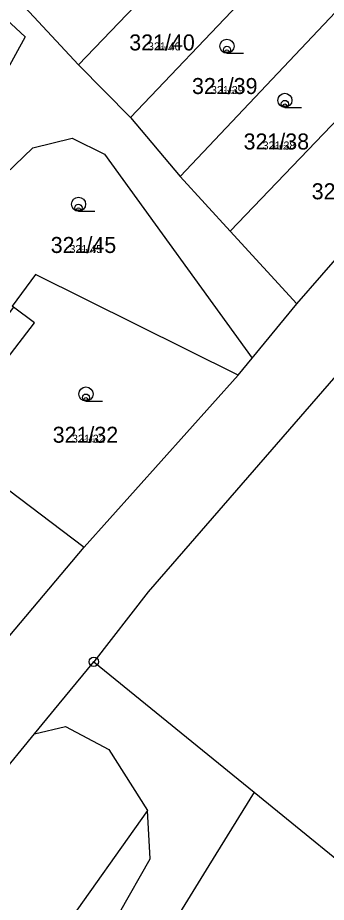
# Model space of a CAD drawing. Extents: x -744652 to -739090, y -980828 to -975855.
# Drawn here: x -742287.7 to -742254.9, y -979035.7 to -978941.8 of the extents above; entities that cross this region are included whole.
import ezdxf

# ---------------------------------------------------------------- set-up
doc = ezdxf.new("R2010")
doc.units = 0
for name, color, linetype in [('KAT_02_hranice parcel', 7, 'Continuous'), ('KAT_03_1000_čísla parcelní', 7, 'Continuous'), ('KAT_03_100_čísla parcelní', 7, 'Continuous'), ('KAT_03_250_čísla parcelní', 7, 'Continuous'), ('KAT_03_500_čísla parcelní', 7, 'Continuous'), ('KAT_05_1000_značky kultur', 7, 'Continuous'), ('KAT_05_100_značky kultur', 7, 'Continuous'), ('KAT_05_250_značky kultur', 7, 'Continuous'), ('KAT_05_500_značky kultur', 7, 'Continuous'), ('KAT_11_značky bodu BP', 7, 'Continuous'), ('KAT_14_plocha_budovy', 7, 'Continuous')]:
    doc.layers.add(name, color=color, linetype=linetype)

msp = doc.modelspace()

# ---------------------------------------------------------------- linework, layer by layer
at = {"layer": 'KAT_02_hranice parcel'}
for p, q in [((-742263.37, -978928.16), (-742281.23, -978946.79)), ((-742213.59, -978933.42), (-742273.84, -979002.73)), ((-742261.82, -978937.76), (-742275.69, -978952.38)), ((-742251.42, -978938.5), (-742270.43, -978958.65)), ((-742286.94, -978940.67), (-742281.23, -978946.79)), ((-742281.23, -978946.79), (-742275.69, -978952.38)), ((-742250.12, -978948.78), (-742265.12, -978964.46)), ((-742258.05, -978972.16), (-742238.5, -978949.68)), ((-742275.69, -978952.38), (-742270.43, -978958.65)), ((-742270.43, -978958.65), (-742265.12, -978964.46)), ((-742265.12, -978964.46), (-742258.05, -978972.16)), ((-742262.77, -978977.93), (-742258.05, -978972.16)), ((-742264.29, -978979.72), (-742262.77, -978977.93)), ((-742280.62, -978998), (-742264.29, -978979.72)), ((-742299.44, -978983.76), (-742280.62, -978998)), ((-742294.46, -979014.4), (-742280.62, -978998)), ((-742273.84, -979002.73), (-742279.6, -979010.17)), ((-742279.6, -979010.17), (-742262.59, -979024.03)), ((-742292.42, -979025.78), (-742285.89, -979017.82))]:
    msp.add_line(p, q, dxfattribs=at)
for points in [[(-742308.88, -978923.38), (-742286.88, -978943.81), (-742292.06, -978953.18)], [(-742296.74, -978965.84), (-742286.06, -978955.59), (-742281.9, -978954.58), (-742278.45, -978956.27), (-742262.77, -978977.93)], [(-742264.29, -978979.72), (-742285.8, -978969.05), (-742288.26, -978972.4)], [(-742299.44, -978983.76), (-742296.73, -978980.32), (-742297.16, -978979.98), (-742296.46, -978979.01), (-742292.21, -978982.34), (-742285.89, -978974.18), (-742288.11, -978972.5), (-742288.26, -978972.4)], [(-742262.59, -979024.03), (-742220.86, -979058.01), (-742196.33, -979029.9), (-742167.92, -978991.13)], [(-742285.89, -979017.82), (-742283.27, -979014.63), (-742279.6, -979010.17)], [(-742285.89, -979017.82), (-742282.59, -979017.03), (-742278, -979019.5), (-742273.89, -979025.95)], [(-742262.59, -979024.03), (-742267.38, -979031.8), (-742279.08, -979050.78), (-742293.94, -979073.94), (-742299.93, -979088.15), (-742311.3, -979111), (-742319.87, -979143.4), (-742317.67, -979155.29), (-742302.74, -979172.98), (-742295.5, -979178.55), (-742289.05, -979181.5), (-742267.99, -979200.3), (-742265.25, -979207.91), (-742258.1, -979217.07), (-742240.98, -979243.05), (-742187.39, -979311.62), (-742172.53, -979335.38), (-742160.86, -979361.17)], [(-742298.15, -979071.24), (-742283.29, -979048.08), (-742273.6, -979031.09), (-742273.89, -979025.95)], [(-742273.89, -979025.95), (-742291.7, -979051.02), (-742298.15, -979071.24)]]:
    msp.add_lwpolyline(points, dxfattribs=at)
at = {"layer": 'KAT_05_1000_značky kultur'}
for p, q in [((-742265.463, -978945.55), (-742263.713, -978945.55)), ((-742259.313, -978951.3), (-742257.563, -978951.3)), ((-742281.223, -978962.33), (-742279.473, -978962.33)), ((-742280.433, -978982.49), (-742278.683, -978982.49))]:
    msp.add_line(p, q, dxfattribs=at)
for centre in [(-742265.463, -978944.8), (-742259.313, -978950.55), (-742281.223, -978961.58), (-742280.433, -978981.74)]:
    msp.add_circle(centre, 0.75, dxfattribs=at)
at = {"layer": 'KAT_05_100_značky kultur'}
for p, q in [((-742265.469, -978945.55), (-742265.294, -978945.55)), ((-742259.319, -978951.3), (-742259.144, -978951.3)), ((-742281.229, -978962.33), (-742281.054, -978962.33)), ((-742280.439, -978982.49), (-742280.264, -978982.49))]:
    msp.add_line(p, q, dxfattribs=at)
for centre in [(-742265.469, -978945.475), (-742259.319, -978951.225), (-742281.229, -978962.255), (-742280.439, -978982.415)]:
    msp.add_circle(centre, 0.075, dxfattribs=at)
at = {"layer": 'KAT_05_250_značky kultur'}
for p, q in [((-742265.468, -978945.55), (-742265.031, -978945.55)), ((-742259.318, -978951.3), (-742258.881, -978951.3)), ((-742281.228, -978962.33), (-742280.791, -978962.33)), ((-742280.438, -978982.49), (-742280.001, -978982.49))]:
    msp.add_line(p, q, dxfattribs=at)
for centre in [(-742265.468, -978945.362), (-742259.318, -978951.112), (-742281.228, -978962.142), (-742280.438, -978982.302)]:
    msp.add_circle(centre, 0.187, dxfattribs=at)
at = {"layer": 'KAT_05_500_značky kultur'}
for p, q in [((-742265.466, -978945.55), (-742264.591, -978945.55)), ((-742259.317, -978951.3), (-742258.442, -978951.3)), ((-742281.226, -978962.33), (-742280.351, -978962.33)), ((-742280.437, -978982.49), (-742279.562, -978982.49))]:
    msp.add_line(p, q, dxfattribs=at)
for centre in [(-742265.466, -978945.175), (-742259.316, -978950.925), (-742281.226, -978961.955), (-742280.436, -978982.115)]:
    msp.add_circle(centre, 0.375, dxfattribs=at)
at = {"layer": 'KAT_11_značky bodu BP'}
for radius in [0.5, 0.0303]:
    msp.add_circle((-742279.6, -979010.17), radius, dxfattribs=at)
at = {"layer": 'KAT_14_plocha_budovy'}
msp.add_lwpolyline([(-742300.12, -978977.68), (-742300.01, -978977.76), (-742297.16, -978979.98), (-742296.46, -978979.01), (-742292.21, -978982.34), (-742285.89, -978974.18), (-742288.11, -978972.5), (-742289.54, -978974.39), (-742290.73, -978973.5), (-742295.01, -978970.21), (-742299.83, -978976.36), (-742299.34, -978976.72)], close=True, dxfattribs=at)

# ---------------------------------------------------------------- texts
at = {"layer": 'KAT_03_1000_čísla parcelní'}
for s, p in [('321/40', (-742275.835, -978945.25)), ('321/39', (-742269.175, -978949.88)), ('321/38', (-742263.695, -978955.77)), ('321/37', (-742256.465, -978961.06)), ('321/45', (-742284.175, -978966.76)), ('321/32', (-742283.965, -978986.91))]:
    msp.add_text(s, height=1.7, dxfattribs=at).set_placement(p)
at = {"layer": 'KAT_03_100_čísla parcelní'}
for s, p in [('321/40', (-742272.269, -978945.25)), ('321/39', (-742265.555, -978949.88)), ('321/38', (-742260.057, -978955.77)), ('321/45', (-742280.591, -978966.76)), ('321/32', (-742280.279, -978986.91))]:
    msp.add_text(s, height=0.17, dxfattribs=at).set_placement(p)
at = {"layer": 'KAT_03_250_čísla parcelní'}
for s, p in [('321/40', (-742272.864, -978945.25)), ('321/39', (-742266.158, -978949.88)), ('321/38', (-742260.663, -978955.77)), ('321/45', (-742281.189, -978966.76)), ('321/32', (-742280.893, -978986.91))]:
    msp.add_text(s, height=0.425, dxfattribs=at).set_placement(p)
at = {"layer": 'KAT_03_500_čísla parcelní'}
for s, p in [('321/40', (-742273.854, -978945.25)), ('321/39', (-742267.164, -978949.88)), ('321/38', (-742261.674, -978955.77)), ('321/45', (-742282.184, -978966.76)), ('321/32', (-742281.917, -978986.91))]:
    msp.add_text(s, height=0.85, dxfattribs=at).set_placement(p)

doc.saveas('drawing.dxf')
